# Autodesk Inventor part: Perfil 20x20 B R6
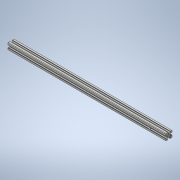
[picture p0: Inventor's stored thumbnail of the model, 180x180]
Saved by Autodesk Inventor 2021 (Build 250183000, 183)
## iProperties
Created: 2020-12
Part Number: Perfil 20x20 B R6
Material: Genérico
Document SubType Name: Modeling
Designer: ATOUZA
Density: 1 g/cm^3
Appearance: Valor por defecto
Author: ATOUZA
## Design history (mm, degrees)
sketch "Boceto1"
  geometry: L1 (4.5, 0.954)-(4.5, 3.232); L2 (4.646, 3.586)-(6.914, 5.854); L3 (7.268, 6)-(8, 6); L4 (8.5, 5.5)-(8.5, 3.6); L5 (9, 3.1)-(9.3, 3.1); L6 (9.5, 3.3)-(9.5, 3.65); L7 (9.5, 3.65)-(9.8, 3.65); L8 (10, 3.85)-(10, 8.5); L9 (8.5, 10)-(3.85, 10); L10 (3.65, 9.8)-(3.65, 9.5); L11 (3.65, 9.5)-(3.3, 9.5); L12 (3.1, 9.3)-(3.1, 9); L13 (3.6, 8.5)-(5.5, 8.5); L14 (6, 8)-(6, 7.268); L15 (5.854, 6.914)-(3.586, 4.646); L16 (3.232, 4.5)-(0.954, 4.5); L17 (0.854, 4.473)-(0.1, 4.038); L18 (-0.1, 4.038)-(-0.854, 4.473); L19 (-0.954, 4.5)-(-3.232, 4.5); L20 (-3.586, 4.646)-(-5.854, 6.914); L21 (-6, 7.268)-(-6, 8); L22 (-5.5, 8.5)-(-3.6, 8.5); L23 (-3.1, 9)-(-3.1, 9.3); L24 (-3.3, 9.5)-(-3.65, 9.5); L25 (-3.65, 9.5)-(-3.65, 9.8); L26 (-3.85, 10)-(-8.5, 10); L27 (-10, 8.5)-(-10, 3.85); L28 (-9.8, 3.65)-(-9.5, 3.65); L29 (-9.5, 3.65)-(-9.5, 3.3); L30 (-9.3, 3.1)-(-9, 3.1); L31 (-8.5, 3.6)-(-8.5, 5.5); L32 (-8, 6)-(-7.268, 6); L33 (-6.914, 5.854)-(-4.646, 3.586); L34 (-4.5, 3.232)-(-4.5, 0.954); L35 (-4.473, 0.854)-(-4.038, 0.1); L36 (-4.038, -0.1)-(-4.473, -0.854); L37 (-4.5, -0.954)-(-4.5, -3.232); L38 (-4.646, -3.586)-(-6.914, -5.854); L39 (-7.268, -6)-(-8, -6); L40 (-8.5, -5.5)-(-8.5, -3.6); L41 (-9, -3.1)-(-9.3, -3.1); L42 (-9.5, -3.3)-(-9.5, -3.65); L43 (-9.5, -3.65)-(-9.8, -3.65); L44 (-10, -3.85)-(-10, -8.5); L45 (-8.5, -10)-(-3.85, -10); L46 (-3.65, -9.8)-(-3.65, -9.5); L47 (-3.65, -9.5)-(-3.3, -9.5); L48 (-3.1, -9.3)-(-3.1, -9); L49 (-3.6, -8.5)-(-5.5, -8.5); L50 (-6, -8)-(-6, -7.268); L51 (-5.854, -6.914)-(-3.586, -4.646); L52 (-3.232, -4.5)-(-0.954, -4.5); L53 (1.258, -2.445)-(1.914, -2.99); L54 (2.992, -1.91)-(2.445, -1.258); L55 (2.445, 1.258)-(2.992, 1.91); L56 (1.914, 2.99)-(1.258, 2.445); L57 (-1.258, 2.445)-(-1.914, 2.99); L58 (-2.992, 1.91)-(-2.445, 1.258); L59 (-2.445, -1.258)-(-2.992, -1.91); L60 (-1.914, -2.99)-(-1.258, -2.445); L61 (1.258, -2.445)-(1.914, -2.99); L62 (2.992, -1.91)-(2.445, -1.258); L63 (2.445, 1.258)-(2.992, 1.91); L64 (1.914, 2.99)-(1.258, 2.445)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; A1 r 0.5 centre (5, 3.232) between (4.646, 3.586) and (4.5, 3.232); A2 r 0.5 centre (7.268, 5.5) between (7.268, 6) and (6.914, 5.854); A3 r 0.5 centre (8, 5.5) between (8.5, 5.5) and (8, 6); A4 r 0.5 centre (9, 3.6) between (8.5, 3.6) and (9, 3.1); A5 r 0.2 centre (9.3, 3.3) between (9.3, 3.1) and (9.5, 3.3); A6 r 0.2 centre (9.8, 3.85) between (9.8, 3.65) and (10, 3.85); A7 r 1.5 centre (8.5, 8.5) between (10, 8.5) and (8.5, 10); A8 r 0.2 centre (3.85, 9.8) between (3.85, 10) and (3.65, 9.8); A9 r 0.2 centre (3.3, 9.3) between (3.3, 9.5) and (3.1, 9.3); A10 r 0.5 centre (3.6, 9) between (3.1, 9) and (3.6, 8.5); A11 r 0.5 centre (5.5, 8) between (6, 8) and (5.5, 8.5); A12 r 0.5 centre (5.5, 7.268) between (5.854, 6.914) and (6, 7.268); A13 r 0.5 centre (3.232, 5) between (3.232, 4.5) and (3.586, 4.646); A14 r 0.2 centre (0.954, 4.3) between (0.954, 4.5) and (0.854, 4.473); A15 r 0.2 centre (0, 4.211) between (-0.1, 4.038) and (0.1, 4.038); A16 r 0.2 centre (-0.954, 4.3) between (-0.854, 4.473) and (-0.954, 4.5); A17 r 0.5 centre (-3.232, 5) between (-3.586, 4.646) and (-3.232, 4.5); A18 r 0.5 centre (-5.5, 7.268) between (-6, 7.268) and (-5.854, 6.914); A19 r 0.5 centre (-5.5, 8) between (-5.5, 8.5) and (-6, 8); A20 r 0.5 centre (-3.6, 9) between (-3.6, 8.5) and (-3.1, 9); A21 r 0.2 centre (-3.3, 9.3) between (-3.1, 9.3) and (-3.3, 9.5); A22 r 0.2 centre (-3.85, 9.8) between (-3.65, 9.8) and (-3.85, 10); A23 r 1.5 centre (-8.5, 8.5) between (-8.5, 10) and (-10, 8.5); A24 r 0.2 centre (-9.8, 3.85) between (-10, 3.85) and (-9.8, 3.65); A25 r 0.2 centre (-9.3, 3.3) between (-9.5, 3.3) and (-9.3, 3.1); A26 r 0.5 centre (-9, 3.6) between (-9, 3.1) and (-8.5, 3.6); A27 r 0.5 centre (-8, 5.5) between (-8, 6) and (-8.5, 5.5); A28 r 0.5 centre (-7.268, 5.5) between (-6.914, 5.854) and (-7.268, 6); A29 r 0.5 centre (-5, 3.232) between (-4.5, 3.232) and (-4.646, 3.586); A30 r 0.2 centre (-4.3, 0.954) between (-4.5, 0.954) and (-4.473, 0.854); A31 r 0.2 centre (-4.211, 0) between (-4.038, -0.1) and (-4.038, 0.1); A32 r 0.2 centre (-4.3, -0.954) between (-4.473, -0.854) and (-4.5, -0.954); A33 r 0.5 centre (-5, -3.232) between (-4.646, -3.586) and (-4.5, -3.232); A34 r 0.5 centre (-7.268, -5.5) between (-7.268, -6) and (-6.914, -5.854); A35 r 0.5 centre (-8, -5.5) between (-8.5, -5.5) and (-8, -6); A36 r 0.5 centre (-9, -3.6) between (-8.5, -3.6) and (-9, -3.1); A37 r 0.2 centre (-9.3, -3.3) between (-9.3, -3.1) and (-9.5, -3.3); A38 r 0.2 centre (-9.8, -3.85) between (-9.8, -3.65) and (-10, -3.85); A39 r 1.5 centre (-8.5, -8.5) between (-10, -8.5) and (-8.5, -10); A40 r 0.2 centre (-3.85, -9.8) between (-3.85, -10) and (-3.65, -9.8); A41 r 0.2 centre (-3.3, -9.3) between (-3.3, -9.5) and (-3.1, -9.3); A42 r 0.5 centre (-3.6, -9) between (-3.1, -9) and (-3.6, -8.5); A43 r 0.5 centre (-5.5, -8) between (-6, -8) and (-5.5, -8.5); A44 r 0.5 centre (-5.5, -7.268) between (-5.854, -6.914) and (-6, -7.268); A45 r 0.5 centre (-3.232, -5) between (-3.232, -4.5) and (-3.586, -4.646); A46 r 2.75 centre (0, 0) between (-1.258, -2.445) and (1.258, -2.445); A47 r 3.55 centre (0, 0) between (1.914, -2.99) and (2.992, -1.91); A48 r 2.75 centre (0, 0) between (2.445, -1.258) and (2.445, 1.258); A49 r 3.55 centre (0, 0) between (2.992, 1.91) and (1.914, 2.99); A50 r 2.75 centre (0, 0) between (1.258, 2.445) and (-1.258, 2.445); A51 r 3.55 centre (0, 0) between (-1.914, 2.99) and (-2.992, 1.91); A52 r 2.75 centre (0, 0) between (-2.445, 1.258) and (-2.445, -1.258); A53 r 3.55 centre (0, 0) between (-2.992, -1.91) and (-1.914, -2.99); A54 r 2.75 centre (0, 0) between (-1.258, -2.445) and (1.258, -2.445); A55 r 3.55 centre (0, 0) between (1.914, -2.99) and (2.992, -1.91); A56 r 2.75 centre (0, 0) between (2.445, -1.258) and (2.445, 1.258); A57 r 3.55 centre (0, 0) between (2.992, 1.91) and (1.914, 2.99); A58 r 2.75 centre (0, 0) between (1.258, 2.445) and (-1.258, 2.445); A59 r 3.55 centre (0, 0) between (-1.914, 2.99) and (-2.992, 1.91); A60 r 2.75 centre (0, 0) between (-2.445, 1.258) and (-2.445, -1.258); A61 r 3.55 centre (0, 0) between (-2.992, -1.91) and (-1.914, -2.99); A62 r 0.5 centre (-8, -5.5) between (-8.5, -5.5) and (-8, -6); A63 r 0.2 centre (-4.211, 0) between (-4.038, -0.1) and (-4.038, 0.1); A64 r 0.5 centre (-7.268, 5.5) between (-6.914, 5.854) and (-7.268, 6)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; 1 further point
  constraints: 324 end point, 198 point on circle, 99 centre point, 2 point on line, 6 other
extrude "Extrusión1" new body sketch "Boceto1" distance "d0" = 480; taper "d1" = 0 deg
sketch "Boceto6"
  geometry: L1 (0, -0.618)-(0, -2.896) reference; L2 (0, 4.65)-(0, 0) reference; L3 (480, -4.804)-(480, -7.082) reference; L4 (0, 0.65)-(480, 0.65) reference; C1 r 2 at (50, -3.85); C2 r 2 at (430, -3.85); C3 r 4.5 at (430, -3.85); C4 r 4.5 at (50, -3.85); 1 further point
  constraints: 4 centre point, 2 coincident, 2 tangent
  dimensions: "d4" = 50 distance from line of L2 C1.centre; "d5" = 4 diameter of C2; "d6" = 50 distance from line of L3 C2.centre; "d7" = 9 diameter of C3; "d8" = 9 diameter of C4; "d9" = 4 diameter of C1
extrude "Extrusión2" cut sketch "Boceto6" extent not by distance; stored distance "d10" = 0; taper "d11" = 0 deg
sketch "Boceto7"
  geometry: L1 (0, -0.618)-(0, -2.896); L2 (0, 4.65)-(0, 0); L3 (480, -4.804)-(480, -7.082); C1 r 2 at (50, -3.85); C2 r 2 at (430, -3.85); C3 r 4.5 at (430, -3.85); C4 r 4.5 at (50, -3.85); 2 further points
  constraints: 6 end point, 4 centre point, 2 coincident
  dimensions: "d12" = 50 distance from line of L2 C1.centre; "d13" = 4 diameter of C2; "d14" = 50 distance from line of L3 C2.centre; "d15" = 9 diameter of C3; "d16" = 9 diameter of C4; "d17" = 4 diameter of C1
extrude "Extrusión3" cut sketch "Boceto7" distance "d18" = 5; taper "d19" = 0 deg
node "Sólido1"
sketch "Boceto5"
  geometry: L1 (0, -3.85)-(450, -3.85)
  constraints: 2 end point
